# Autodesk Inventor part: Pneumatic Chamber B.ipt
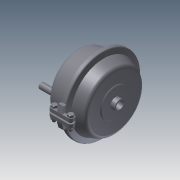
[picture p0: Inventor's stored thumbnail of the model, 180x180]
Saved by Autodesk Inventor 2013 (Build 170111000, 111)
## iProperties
Created: 2005-03
Part Number: Pneumatic Chamber B.ipt
Material: Steel, Mild
Document SubType Name: Modeling
Designer: salex
Manufacturer: Standard
Standards Organization: Custom
Density: 7.86 g/cm^3
Mass: 18779.2 g
Surface Area: 1282.96 cm^2
Volume: 2389.21 cm^3
Author: salex
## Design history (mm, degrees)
body "Solid1"
derived "PNEVMOCAM.iam"
node "M8-6gx35.58.019(S13).ipt:1"
node "M8-6gx35.58.019(S13).ipt:2"
node "M8-6H.5.019(S13).ipt:1"
node "M8-6H.5.019(S13).ipt:2"
node "PNEVMOCAM PART1.ipt:2"
node "PNEVMOCAM PART2.ipt:3"
node "PNEVMOCAM PART2.ipt:4"
